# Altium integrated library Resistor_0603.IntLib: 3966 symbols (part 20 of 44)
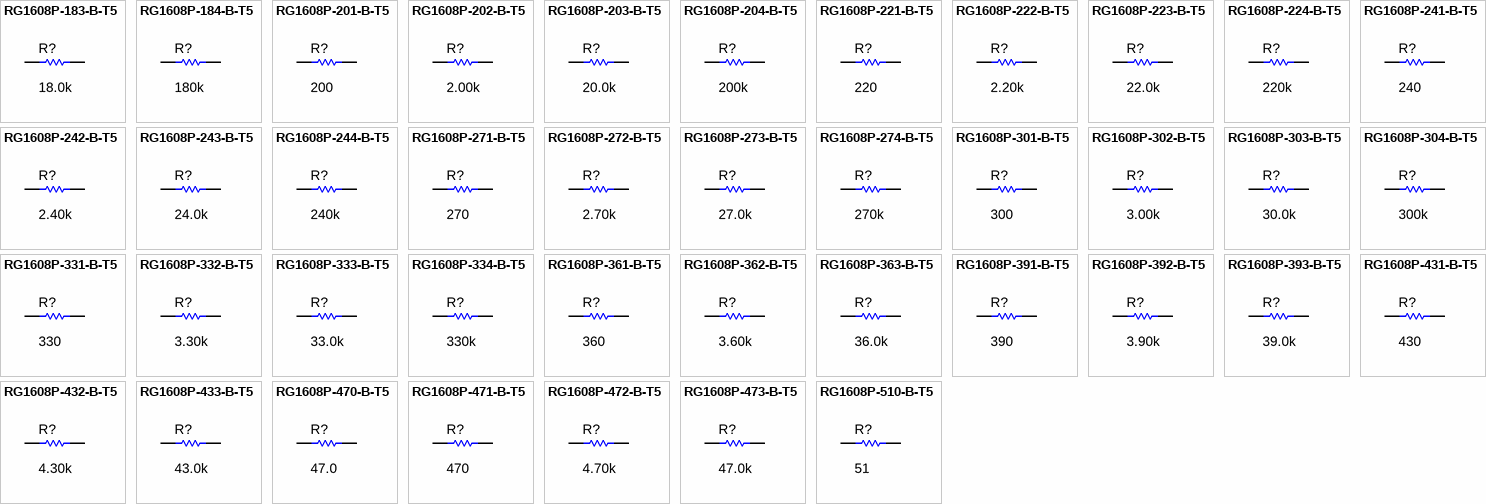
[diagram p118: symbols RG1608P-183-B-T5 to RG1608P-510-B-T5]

## RG1608P-431-B-T5
designator R?  ValueDisplayed: 430  (hidden comment: RG1608P-431-B-T5)
RES, 430, 0.1%, 0.1 W, 0603; Manufacturer: Susumu Co Ltd; CompType: Resistor; Value: 430; Value_Code: 430R; Tolerance_%: 0.1; Value2: 0.1W; VDC_V: 75; TempCo: 25 ppm/C; SizeArea_mm2: 1.28; SizeX_mm: 1.6; SizeY_mm: 0.8; SizeZ_mm: 1; U/M: EA; AEC Category: Q200
signal-integrity model Resistor
simulation model Resistor
footprint 0603
footprint 0603M
footprint 0603L
footprint 0603_HV
footprint 0603S
pins: 1, 2

## RG1608P-432-B-T5
designator R?  ValueDisplayed: 4.30k  (hidden comment: RG1608P-432-B-T5)
RES, 4.30 k, 0.1%, 0.1 W, 0603; Manufacturer: Susumu Co Ltd; CompType: Resistor; Value: 4.30k; Res_ohm: 4300; Value_Code: 4k30; Tolerance_%: 0.1; Value2: 0.1W; VDC_V: 75; TempCo: 25 ppm/C; SizeArea_mm2: 1.28; SizeX_mm: 1.6; SizeY_mm: 0.8; SizeZ_mm: 1; U/M: EA; AEC Category: Q200
signal-integrity model Resistor
simulation model Resistor
footprint 0603
footprint 0603M
footprint 0603L
footprint 0603_HV
footprint 0603S
pins: 1, 2

## RG1608P-433-B-T5
designator R?  ValueDisplayed: 43.0k  (hidden comment: RG1608P-433-B-T5)
RES, 43.0 k, 0.1%, 0.1 W, 0603; Manufacturer: Susumu Co Ltd; CompType: Resistor; Value: 43.0k; Res_ohm: 43000; Value_Code: 43k0; Tolerance_%: 0.1; Value2: 0.1W; VDC_V: 75; TempCo: 25 ppm/C; SizeArea_mm2: 1.28; SizeX_mm: 1.6; SizeY_mm: 0.8; SizeZ_mm: 1; U/M: EA; AEC Category: Q200
signal-integrity model Resistor
simulation model Resistor
footprint 0603
footprint 0603M
footprint 0603L
footprint 0603_HV
footprint 0603S
pins: 1, 2

## RG1608P-470-B-T5
designator R?  ValueDisplayed: 47.0  (hidden comment: RG1608P-470-B-T5)
RES, 47.0, 0.1%, 0.1 W, 0603; Manufacturer: Susumu Co Ltd; CompType: Resistor; Value: 47.0; Res_ohm: 47; Value_Code: 47R0; Tolerance_%: 0.1; Value2: 0.1W; VDC_V: 75; TempCo: 25 ppm/C; SizeArea_mm2: 1.28; SizeX_mm: 1.6; SizeY_mm: 0.8; SizeZ_mm: 1; EIA_Code: E192; U/M: EA; AEC Category: Q200
signal-integrity model Resistor
simulation model Resistor
footprint 0603
footprint 0603M
footprint 0603L
footprint 0603_HV
footprint 0603S
pins: 1, 2

## RG1608P-471-B-T5
designator R?  ValueDisplayed: 470  (hidden comment: RG1608P-471-B-T5)
RES, 470, 0.1%, 0.1 W, 0603; Manufacturer: Susumu Co Ltd; CompType: Resistor; Value: 470; Value_Code: 470R; Tolerance_%: 0.1; Value2: 0.1W; VDC_V: 75; TempCo: 25 ppm/C; SizeArea_mm2: 1.28; SizeX_mm: 1.6; SizeY_mm: 0.8; SizeZ_mm: 1; EIA_Code: E192; U/M: EA; AEC Category: Q200
signal-integrity model Resistor
simulation model Resistor
footprint 0603
footprint 0603M
footprint 0603L
footprint 0603_HV
footprint 0603S
pins: 1, 2

## RG1608P-472-B-T5
designator R?  ValueDisplayed: 4.70k  (hidden comment: RG1608P-472-B-T5)
RES, 4.70 k, 0.1%, 0.1 W, 0603; Manufacturer: Susumu Co Ltd; CompType: Resistor; Value: 4.70k; Res_ohm: 4700; Value_Code: 4k70; Tolerance_%: 0.1; Value2: 0.1W; VDC_V: 75; TempCo: 25 ppm/C; SizeArea_mm2: 1.28; SizeX_mm: 1.6; SizeY_mm: 0.8; SizeZ_mm: 1; EIA_Code: E192; U/M: EA; AEC Category: Q200; Green_Lifecycle: Active; Green_REACh: Passed
signal-integrity model Resistor
simulation model Resistor
footprint 0603
footprint 0603M
footprint 0603L
footprint 0603_HV
footprint 0603S
pins: 1, 2

## RG1608P-473-B-T5
designator R?  ValueDisplayed: 47.0k  (hidden comment: RG1608P-473-B-T5)
RES, 47.0 k, 0.1%, 0.1 W, 0603; Manufacturer: Susumu Co Ltd; CompType: Resistor; Value: 47.0k; Res_ohm: 47000; Value_Code: 47k0; Tolerance_%: 0.1; Value2: 0.1W; VDC_V: 75; TempCo: 25 ppm/C; SizeArea_mm2: 1.28; SizeX_mm: 1.6; SizeY_mm: 0.8; SizeZ_mm: 1; EIA_Code: E192; U/M: EA; AEC Category: Q200
signal-integrity model Resistor
simulation model Resistor
footprint 0603
footprint 0603M
footprint 0603L
footprint 0603_HV
footprint 0603S
pins: 1, 2

## RG1608P-510-B-T5
designator R?  ValueDisplayed: 51  (hidden comment: RG1608P-510-B-T5)
RES, 51, 0.1%, 0.1 W, 0603; Manufacturer: Susumu Co Ltd; CompType: Resistor; Value: 51; Value_Code: 51R0; Tolerance_%: 0.1; Value2: 0.1W; VDC_V: 75; TempCo: 25 ppm/C; SizeArea_mm2: 1.28; SizeX_mm: 1.6; SizeY_mm: 0.8; SizeZ_mm: 1; U/M: EA; AEC Category: Q200
signal-integrity model Resistor
simulation model Resistor
footprint 0603
footprint 0603M
footprint 0603L
footprint 0603_HV
footprint 0603S
pins: 1, 2

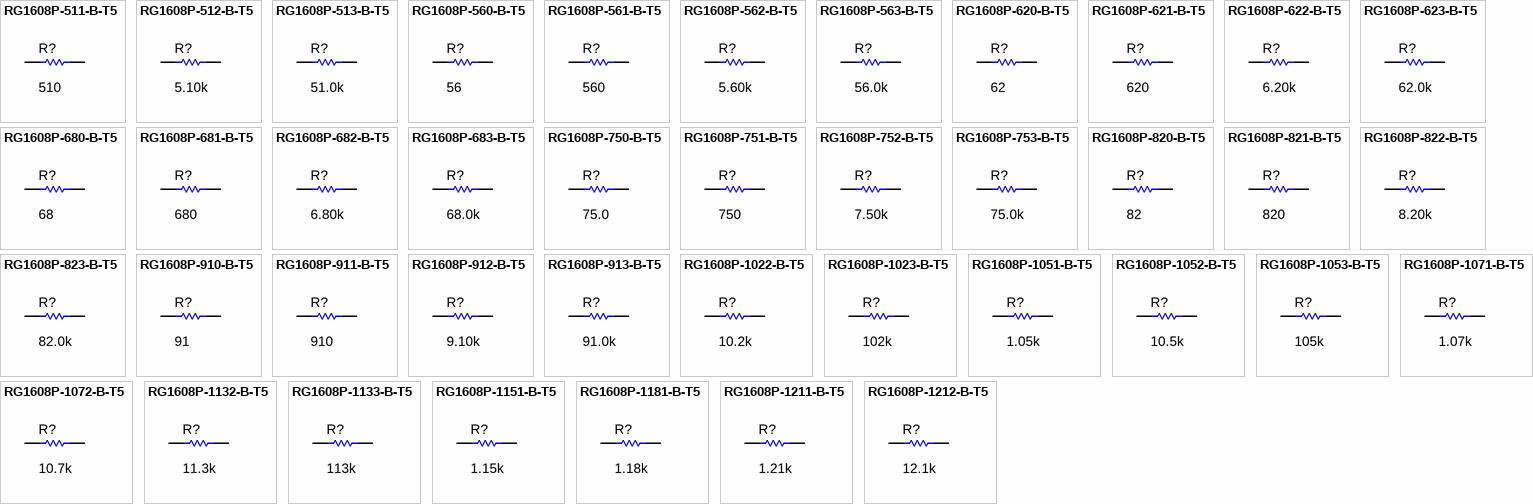
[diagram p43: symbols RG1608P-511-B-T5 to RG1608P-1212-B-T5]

## RG1608P-511-B-T5
designator R?  ValueDisplayed: 510  (hidden comment: RG1608P-511-B-T5)
RES, 510, 0.1%, 0.1 W, 0603; Manufacturer: Susumu Co Ltd; CompType: Resistor; Value: 510; Value_Code: 510R; Tolerance_%: 0.1; Value2: 0.1W; VDC_V: 75; TempCo: 25 ppm/C; SizeArea_mm2: 1.28; SizeX_mm: 1.6; SizeY_mm: 0.8; SizeZ_mm: 1; U/M: EA; AEC Category: Q200
signal-integrity model Resistor
simulation model Resistor
footprint 0603
footprint 0603M
footprint 0603L
footprint 0603_HV
footprint 0603S
pins: 1, 2

## RG1608P-512-B-T5
designator R?  ValueDisplayed: 5.10k  (hidden comment: RG1608P-512-B-T5)
RES, 5.10 k, 0.1%, 0.1 W, 0603; Manufacturer: Susumu Co Ltd; CompType: Resistor; Value: 5.10k; Res_ohm: 5100; Value_Code: 5k10; Tolerance_%: 0.1; Value2: 0.1W; VDC_V: 75; TempCo: 25 ppm/C; SizeArea_mm2: 1.28; SizeX_mm: 1.6; SizeY_mm: 0.8; SizeZ_mm: 1; U/M: EA; AEC Category: Q200
signal-integrity model Resistor
simulation model Resistor
footprint 0603
footprint 0603M
footprint 0603L
footprint 0603_HV
footprint 0603S
pins: 1, 2

## RG1608P-513-B-T5
designator R?  ValueDisplayed: 51.0k  (hidden comment: RG1608P-513-B-T5)
RES, 51.0 k, 0.1%, 0.1 W, 0603; Manufacturer: Susumu Co Ltd; CompType: Resistor; Value: 51.0k; Res_ohm: 51000; Value_Code: 51k0; Tolerance_%: 0.1; Value2: 0.1W; VDC_V: 75; TempCo: 25 ppm/C; SizeArea_mm2: 1.28; SizeX_mm: 1.6; SizeY_mm: 0.8; SizeZ_mm: 1; U/M: EA; AEC Category: Q200
signal-integrity model Resistor
simulation model Resistor
footprint 0603
footprint 0603M
footprint 0603L
footprint 0603_HV
footprint 0603S
pins: 1, 2

## RG1608P-560-B-T5
designator R?  ValueDisplayed: 56  (hidden comment: RG1608P-560-B-T5)
RES, 56, 0.1%, 0.1 W, 0603; Manufacturer: Susumu Co Ltd; CompType: Resistor; Value: 56; Value_Code: 56R0; Tolerance_%: 0.1; Value2: 0.1W; VDC_V: 75; TempCo: 25 ppm/C; SizeArea_mm2: 1.28; SizeX_mm: 1.6; SizeY_mm: 0.8; SizeZ_mm: 1; U/M: EA; AEC Category: Q200
signal-integrity model Resistor
simulation model Resistor
footprint 0603
footprint 0603M
footprint 0603L
footprint 0603_HV
footprint 0603S
pins: 1, 2

## RG1608P-561-B-T5
designator R?  ValueDisplayed: 560  (hidden comment: RG1608P-561-B-T5)
RES, 560, 0.1%, 0.1 W, 0603; Manufacturer: Susumu Co Ltd; CompType: Resistor; Value: 560; Value_Code: 560R; Tolerance_%: 0.1; Value2: 0.1W; VDC_V: 75; TempCo: 25 ppm/C; SizeArea_mm2: 1.28; SizeX_mm: 1.6; SizeY_mm: 0.8; SizeZ_mm: 1; U/M: EA; AEC Category: Q200
signal-integrity model Resistor
simulation model Resistor
footprint 0603
footprint 0603M
footprint 0603L
footprint 0603_HV
footprint 0603S
pins: 1, 2

## RG1608P-562-B-T5
designator R?  ValueDisplayed: 5.60k  (hidden comment: RG1608P-562-B-T5)
RES, 5.60 k, 0.1%, 0.1 W, 0603; Manufacturer: Susumu Co Ltd; CompType: Resistor; Value: 5.60k; Res_ohm: 5600; Value_Code: 5k60; Tolerance_%: 0.1; Value2: 0.1W; VDC_V: 75; TempCo: 25 ppm/C; SizeArea_mm2: 1.28; SizeX_mm: 1.6; SizeY_mm: 0.8; SizeZ_mm: 1; U/M: EA; AEC Category: Q200
signal-integrity model Resistor
simulation model Resistor
footprint 0603
footprint 0603M
footprint 0603L
footprint 0603_HV
footprint 0603S
pins: 1, 2

## RG1608P-563-B-T5
designator R?  ValueDisplayed: 56.0k  (hidden comment: RG1608P-563-B-T5)
RES, 56.0 k, 0.1%, 0.1 W, 0603; Manufacturer: Susumu Co Ltd; CompType: Resistor; Value: 56.0k; Res_ohm: 56000; Value_Code: 56k0; Tolerance_%: 0.1; Value2: 0.1W; VDC_V: 75; TempCo: 25 ppm/C; SizeArea_mm2: 1.28; SizeX_mm: 1.6; SizeY_mm: 0.8; SizeZ_mm: 1; U/M: EA; AEC Category: Q200
signal-integrity model Resistor
simulation model Resistor
footprint 0603
footprint 0603M
footprint 0603L
footprint 0603_HV
footprint 0603S
pins: 1, 2

## RG1608P-620-B-T5
designator R?  ValueDisplayed: 62  (hidden comment: RG1608P-620-B-T5)
RES, 62, 0.1%, 0.1 W, 0603; Manufacturer: Susumu Co Ltd; CompType: Resistor; Value: 62; Value_Code: 62R0; Tolerance_%: 0.1; Value2: 0.1W; VDC_V: 75; TempCo: 25 ppm/C; SizeArea_mm2: 1.28; SizeX_mm: 1.6; SizeY_mm: 0.8; SizeZ_mm: 1; U/M: EA; AEC Category: Q200
signal-integrity model Resistor
simulation model Resistor
footprint 0603
footprint 0603M
footprint 0603L
footprint 0603_HV
footprint 0603S
pins: 1, 2

## RG1608P-621-B-T5
designator R?  ValueDisplayed: 620  (hidden comment: RG1608P-621-B-T5)
RES, 620, 0.1%, 0.1 W, 0603; Manufacturer: Susumu Co Ltd; CompType: Resistor; Value: 620; Value_Code: 620R; Tolerance_%: 0.1; Value2: 0.1W; VDC_V: 75; TempCo: 25 ppm/C; SizeArea_mm2: 1.28; SizeX_mm: 1.6; SizeY_mm: 0.8; SizeZ_mm: 1; U/M: EA; AEC Category: Q200
signal-integrity model Resistor
simulation model Resistor
footprint 0603
footprint 0603M
footprint 0603L
footprint 0603_HV
footprint 0603S
pins: 1, 2

## RG1608P-622-B-T5
designator R?  ValueDisplayed: 6.20k  (hidden comment: RG1608P-622-B-T5)
RES, 6.20 k, 0.1%, 0.1 W, 0603; Manufacturer: Susumu Co Ltd; CompType: Resistor; Value: 6.20k; Res_ohm: 6200; Value_Code: 6k20; Tolerance_%: 0.1; Value2: 0.1W; VDC_V: 75; TempCo: 25 ppm/C; SizeArea_mm2: 1.28; SizeX_mm: 1.6; SizeY_mm: 0.8; SizeZ_mm: 1; U/M: EA; AEC Category: Q200
signal-integrity model Resistor
simulation model Resistor
footprint 0603
footprint 0603M
footprint 0603L
footprint 0603_HV
footprint 0603S
pins: 1, 2

## RG1608P-623-B-T5
designator R?  ValueDisplayed: 62.0k  (hidden comment: RG1608P-623-B-T5)
RES, 62.0 k, 0.1%, 0.1 W, 0603; Manufacturer: Susumu Co Ltd; CompType: Resistor; Value: 62.0k; Res_ohm: 62000; Value_Code: 62k0; Tolerance_%: 0.1; Value2: 0.1W; VDC_V: 75; TempCo: 25 ppm/C; SizeArea_mm2: 1.28; SizeX_mm: 1.6; SizeY_mm: 0.8; SizeZ_mm: 1; U/M: EA; AEC Category: Q200
signal-integrity model Resistor
simulation model Resistor
footprint 0603
footprint 0603M
footprint 0603L
footprint 0603_HV
footprint 0603S
pins: 1, 2

## RG1608P-680-B-T5
designator R?  ValueDisplayed: 68  (hidden comment: RG1608P-680-B-T5)
RES, 68, 0.1%, 0.1 W, 0603; Manufacturer: Susumu Co Ltd; CompType: Resistor; Value: 68; Value_Code: 68R0; Tolerance_%: 0.1; Value2: 0.1W; VDC_V: 75; TempCo: 25 ppm/C; SizeArea_mm2: 1.28; SizeX_mm: 1.6; SizeY_mm: 0.8; SizeZ_mm: 1; U/M: EA; AEC Category: Q200
signal-integrity model Resistor
simulation model Resistor
footprint 0603
footprint 0603M
footprint 0603L
footprint 0603_HV
footprint 0603S
pins: 1, 2

## RG1608P-681-B-T5
designator R?  ValueDisplayed: 680  (hidden comment: RG1608P-681-B-T5)
RES, 680, 0.1%, 0.1 W, 0603; Manufacturer: Susumu Co Ltd; CompType: Resistor; Value: 680; Value_Code: 680R; Tolerance_%: 0.1; Value2: 0.1W; VDC_V: 75; TempCo: 25 ppm/C; SizeArea_mm2: 1.28; SizeX_mm: 1.6; SizeY_mm: 0.8; SizeZ_mm: 1; U/M: EA; AEC Category: Q200
signal-integrity model Resistor
simulation model Resistor
footprint 0603
footprint 0603M
footprint 0603L
footprint 0603_HV
footprint 0603S
pins: 1, 2

## RG1608P-682-B-T5
designator R?  ValueDisplayed: 6.80k  (hidden comment: RG1608P-682-B-T5)
RES, 6.80 k, 0.1%, 0.1 W, 0603; Manufacturer: Susumu Co Ltd; CompType: Resistor; Value: 6.80k; Res_ohm: 6800; Value_Code: 6k80; Tolerance_%: 0.1; Value2: 0.1W; VDC_V: 75; TempCo: 25 ppm/C; SizeArea_mm2: 1.28; SizeX_mm: 1.6; SizeY_mm: 0.8; SizeZ_mm: 1; U/M: EA; AEC Category: Q200
signal-integrity model Resistor
simulation model Resistor
footprint 0603
footprint 0603M
footprint 0603L
footprint 0603_HV
footprint 0603S
pins: 1, 2

## RG1608P-683-B-T5
designator R?  ValueDisplayed: 68.0k  (hidden comment: RG1608P-683-B-T5)
RES, 68.0 k, 0.1%, 0.1 W, 0603; Manufacturer: Susumu Co Ltd; CompType: Resistor; Value: 68.0k; Res_ohm: 68000; Value_Code: 68k0; Tolerance_%: 0.1; Value2: 0.1W; VDC_V: 75; TempCo: 25 ppm/C; SizeArea_mm2: 1.28; SizeX_mm: 1.6; SizeY_mm: 0.8; SizeZ_mm: 1; U/M: EA; AEC Category: Q200
signal-integrity model Resistor
simulation model Resistor
footprint 0603
footprint 0603M
footprint 0603L
footprint 0603_HV
footprint 0603S
pins: 1, 2

## RG1608P-750-B-T5
designator R?  ValueDisplayed: 75.0  (hidden comment: RG1608P-750-B-T5)
RES, 75.0, 0.1%, 0.1 W, 0603; Manufacturer: Susumu Co Ltd; CompType: Resistor; Value: 75.0; Res_ohm: 75; Value_Code: 75R0; Tolerance_%: 0.1; Value2: 0.1W; TempCo: 25 ppm/C; SizeArea_mm2: 1.28; SizeX_mm: 1.6; SizeY_mm: 0.8; SizeZ_mm: 1; EIA_Code: E192; U/M: EA; AEC Category: Q200
signal-integrity model Resistor
simulation model Resistor
footprint 0603
footprint 0603M
footprint 0603L
footprint 0603_HV
footprint 0603S
pins: 1, 2

## RG1608P-751-B-T5
designator R?  ValueDisplayed: 750  (hidden comment: RG1608P-751-B-T5)
RES, 750, 0.1%, 0.1 W, 0603; Manufacturer: Susumu Co Ltd; CompType: Resistor; Value: 750; Value_Code: 750R; Tolerance_%: 0.1; Value2: 0.1W; VDC_V: 75; TempCo: 25 ppm/C; SizeArea_mm2: 1.28; SizeX_mm: 1.6; SizeY_mm: 0.8; SizeZ_mm: 1; EIA_Code: E192; U/M: EA; AEC Category: Q200
signal-integrity model Resistor
simulation model Resistor
footprint 0603
footprint 0603M
footprint 0603L
footprint 0603_HV
footprint 0603S
pins: 1, 2

## RG1608P-752-B-T5
designator R?  ValueDisplayed: 7.50k  (hidden comment: RG1608P-752-B-T5)
RES, 7.50 k, 0.1%, 0.1 W, 0603; Manufacturer: Susumu Co Ltd; CompType: Resistor; Value: 7.50k; Res_ohm: 7500; Value_Code: 7k50; Tolerance_%: 0.1; Value2: 0.1W; VDC_V: 75; TempCo: 25 ppm/C; SizeArea_mm2: 1.28; SizeX_mm: 1.6; SizeY_mm: 0.8; SizeZ_mm: 1; EIA_Code: E192; U/M: EA; AEC Category: Q200
signal-integrity model Resistor
simulation model Resistor
footprint 0603
footprint 0603M
footprint 0603L
footprint 0603_HV
footprint 0603S
pins: 1, 2

## RG1608P-753-B-T5
designator R?  ValueDisplayed: 75.0k  (hidden comment: RG1608P-753-B-T5)
RES, 75.0 k, 0.1%, 0.1 W, 0603; Manufacturer: Susumu Co Ltd; CompType: Resistor; Value: 75.0k; Res_ohm: 75000; Value_Code: 75k0; Tolerance_%: 0.1; Value2: 0.1W; VDC_V: 75; TempCo: 25 ppm/C; SizeArea_mm2: 1.28; SizeX_mm: 1.6; SizeY_mm: 0.8; SizeZ_mm: 1; EIA_Code: E192; U/M: EA; AEC Category: Q200
signal-integrity model Resistor
simulation model Resistor
footprint 0603
footprint 0603M
footprint 0603L
footprint 0603_HV
footprint 0603S
pins: 1, 2

## RG1608P-820-B-T5
designator R?  ValueDisplayed: 82  (hidden comment: RG1608P-820-B-T5)
RES, 82, 0.1%, 0.1 W, 0603; Manufacturer: Susumu Co Ltd; CompType: Resistor; Value: 82; Value_Code: 82R0; Tolerance_%: 0.1; Value2: 0.1W; VDC_V: 75; TempCo: 25 ppm/C; SizeArea_mm2: 1.28; SizeX_mm: 1.6; SizeY_mm: 0.8; SizeZ_mm: 1; U/M: EA; AEC Category: Q200
signal-integrity model Resistor
simulation model Resistor
footprint 0603
footprint 0603M
footprint 0603L
footprint 0603_HV
footprint 0603S
pins: 1, 2

## RG1608P-821-B-T5
designator R?  ValueDisplayed: 820  (hidden comment: RG1608P-821-B-T5)
RES, 820, 0.1%, 0.1 W, 0603; Manufacturer: Susumu Co Ltd; CompType: Resistor; Value: 820; Value_Code: 820R; Tolerance_%: 0.1; Value2: 0.1W; VDC_V: 75; TempCo: 25 ppm/C; SizeArea_mm2: 1.28; SizeX_mm: 1.6; SizeY_mm: 0.8; SizeZ_mm: 1; U/M: EA; AEC Category: Q200
signal-integrity model Resistor
simulation model Resistor
footprint 0603
footprint 0603M
footprint 0603L
footprint 0603_HV
footprint 0603S
pins: 1, 2

## RG1608P-822-B-T5
designator R?  ValueDisplayed: 8.20k  (hidden comment: RG1608P-822-B-T5)
RES, 8.20 k, 0.1%, 0.1 W, 0603; Manufacturer: Susumu Co Ltd; CompType: Resistor; Value: 8.20k; Res_ohm: 8200; Value_Code: 8k20; Tolerance_%: 0.1; Value2: 0.1W; VDC_V: 75; TempCo: 25 ppm/C; SizeArea_mm2: 1.28; SizeX_mm: 1.6; SizeY_mm: 0.8; SizeZ_mm: 1; U/M: EA; AEC Category: Q200
signal-integrity model Resistor
simulation model Resistor
footprint 0603
footprint 0603M
footprint 0603L
footprint 0603_HV
footprint 0603S
pins: 1, 2

## RG1608P-823-B-T5
designator R?  ValueDisplayed: 82.0k  (hidden comment: RG1608P-823-B-T5)
RES, 82.0 k, 0.1%, 0.1 W, 0603; Manufacturer: Susumu Co Ltd; CompType: Resistor; Value: 82.0k; Res_ohm: 82000; Value_Code: 82k0; Tolerance_%: 0.1; Value2: 0.1W; VDC_V: 75; TempCo: 25 ppm/C; SizeArea_mm2: 1.28; SizeX_mm: 1.6; SizeY_mm: 0.8; SizeZ_mm: 1; U/M: EA; AEC Category: Q200
signal-integrity model Resistor
simulation model Resistor
footprint 0603
footprint 0603M
footprint 0603L
footprint 0603_HV
footprint 0603S
pins: 1, 2

## RG1608P-910-B-T5
designator R?  ValueDisplayed: 91  (hidden comment: RG1608P-910-B-T5)
RES, 91, 0.1%, 0.1 W, 0603; Manufacturer: Susumu Co Ltd; CompType: Resistor; Value: 91; Value_Code: 91R0; Tolerance_%: 0.1; Value2: 0.1W; VDC_V: 75; TempCo: 25 ppm/C; SizeArea_mm2: 1.28; SizeX_mm: 1.6; SizeY_mm: 0.8; SizeZ_mm: 1; U/M: EA; AEC Category: Q200
signal-integrity model Resistor
simulation model Resistor
footprint 0603
footprint 0603M
footprint 0603L
footprint 0603_HV
footprint 0603S
pins: 1, 2

## RG1608P-911-B-T5
designator R?  ValueDisplayed: 910  (hidden comment: RG1608P-911-B-T5)
RES, 910, 0.1%, 0.1 W, 0603; Manufacturer: Susumu Co Ltd; CompType: Resistor; Value: 910; Value_Code: 910R; Tolerance_%: 0.1; Value2: 0.1W; VDC_V: 75; TempCo: 25 ppm/C; SizeArea_mm2: 1.28; SizeX_mm: 1.6; SizeY_mm: 0.8; SizeZ_mm: 1; U/M: EA; AEC Category: Q200
signal-integrity model Resistor
simulation model Resistor
footprint 0603
footprint 0603M
footprint 0603L
footprint 0603_HV
footprint 0603S
pins: 1, 2

## RG1608P-912-B-T5
designator R?  ValueDisplayed: 9.10k  (hidden comment: RG1608P-912-B-T5)
RES, 9.10 k, 0.1%, 0.1 W, 0603; Manufacturer: Susumu Co Ltd; CompType: Resistor; Value: 9.10k; Res_ohm: 9100; Value_Code: 9k10; Tolerance_%: 0.1; Value2: 0.1W; VDC_V: 75; TempCo: 25 ppm/C; SizeArea_mm2: 1.28; SizeX_mm: 1.6; SizeY_mm: 0.8; SizeZ_mm: 1; U/M: EA; AEC Category: Q200
signal-integrity model Resistor
simulation model Resistor
footprint 0603
footprint 0603M
footprint 0603L
footprint 0603_HV
footprint 0603S
pins: 1, 2

## RG1608P-913-B-T5
designator R?  ValueDisplayed: 91.0k  (hidden comment: RG1608P-913-B-T5)
RES, 91.0 k, 0.1%, 0.1 W, 0603; Manufacturer: Susumu Co Ltd; CompType: Resistor; Value: 91.0k; Res_ohm: 91000; Value_Code: 91k0; Tolerance_%: 0.1; Value2: 0.1W; VDC_V: 75; TempCo: 25 ppm/C; SizeArea_mm2: 1.28; SizeX_mm: 1.6; SizeY_mm: 0.8; SizeZ_mm: 1; U/M: EA; AEC Category: Q200
signal-integrity model Resistor
simulation model Resistor
footprint 0603
footprint 0603M
footprint 0603L
footprint 0603_HV
footprint 0603S
pins: 1, 2

## RG1608P-1022-B-T5
designator R?  ValueDisplayed: 10.2k  (hidden comment: RG1608P-1022-B-T5)
RES, 10.2 k, 0.1%, 0.1 W, 0603; Manufacturer: Susumu Co Ltd; CompType: Resistor; Value: 10.2k; Res_ohm: 10200; Value_Code: 10k2; Tolerance_%: 0.1; Value2: 0.1W; VDC_V: 75; TempCo: 25 ppm/C; SizeArea_mm2: 1.28; SizeX_mm: 1.6; SizeY_mm: 0.8; SizeZ_mm: 1; EIA_Code: E192; U/M: EA; AEC Category: Q200
signal-integrity model Resistor
simulation model Resistor
footprint 0603
footprint 0603M
footprint 0603L
footprint 0603_HV
footprint 0603S
pins: 1, 2

## RG1608P-1023-B-T5
designator R?  ValueDisplayed: 102k  (hidden comment: RG1608P-1023-B-T5)
RES, 102 k, 0.1%, 0.1 W, 0603; Manufacturer: Susumu Co Ltd; CompType: Resistor; Value: 102k; Res_ohm: 102000; Tolerance_%: 0.1; Value2: 0.1W; VDC_V: 75; TempCo: 25 ppm/C; SizeArea_mm2: 1.28; SizeX_mm: 1.6; SizeY_mm: 0.8; SizeZ_mm: 1; EIA_Code: E192; U/M: EA; AEC Category: Q200; Green_Lifecycle: Active; Green_REACh: Passed
signal-integrity model Resistor
simulation model Resistor
footprint 0603
footprint 0603M
footprint 0603L
footprint 0603_HV
footprint 0603S
pins: 1, 2

## RG1608P-1051-B-T5
designator R?  ValueDisplayed: 1.05k  (hidden comment: RG1608P-1051-B-T5)
RES, 1.05 k, 0.1%, 0.1 W, 0603; Manufacturer: Susumu Co Ltd; CompType: Resistor; Value: 1.05k; Res_ohm: 1050; Value_Code: 1k05; Tolerance_%: 0.1; Value2: 0.1W; VDC_V: 75; TempCo: 25 ppm/C; SizeArea_mm2: 1.28; SizeX_mm: 1.6; SizeY_mm: 0.8; SizeZ_mm: 1; EIA_Code: E192; U/M: EA; AEC Category: Q200
signal-integrity model Resistor
simulation model Resistor
footprint 0603
footprint 0603M
footprint 0603L
footprint 0603_HV
footprint 0603S
pins: 1, 2

## RG1608P-1052-B-T5
designator R?  ValueDisplayed: 10.5k  (hidden comment: RG1608P-1052-B-T5)
RES, 10.5 k, 0.1%, 0.1 W, 0603; Manufacturer: Susumu Co Ltd; CompType: Resistor; Value: 10.5k; Res_ohm: 10500; Value_Code: 10k5; Tolerance_%: 0.1; Value2: 0.1W; VDC_V: 75; TempCo: 25 ppm/C; SizeArea_mm2: 1.28; SizeX_mm: 1.6; SizeY_mm: 0.8; SizeZ_mm: 1; EIA_Code: E192; U/M: EA; AEC Category: Q200
signal-integrity model Resistor
simulation model Resistor
footprint 0603
footprint 0603M
footprint 0603L
footprint 0603_HV
footprint 0603S
pins: 1, 2

## RG1608P-1053-B-T5
designator R?  ValueDisplayed: 105k  (hidden comment: RG1608P-1053-B-T5)
RES, 105 k, 0.1%, 0.1 W, 0603; Manufacturer: Susumu Co Ltd; CompType: Resistor; Value: 105k; Res_ohm: 105000; Tolerance_%: 0.1; Value2: 0.1W; VDC_V: 75; TempCo: 25 ppm/C; SizeArea_mm2: 1.28; SizeX_mm: 1.6; SizeY_mm: 0.8; SizeZ_mm: 1; EIA_Code: E192; U/M: EA; AEC Category: Q200
signal-integrity model Resistor
simulation model Resistor
footprint 0603
footprint 0603M
footprint 0603L
footprint 0603_HV
footprint 0603S
pins: 1, 2

## RG1608P-1071-B-T5
designator R?  ValueDisplayed: 1.07k  (hidden comment: RG1608P-1071-B-T5)
RES, 1.07 k, 0.1%, 0.1 W, 0603; Manufacturer: Susumu Co Ltd; CompType: Resistor; Value: 1.07k; Res_ohm: 1070; Value_Code: 1k07; Tolerance_%: 0.1; Value2: 0.1W; VDC_V: 75; TempCo: 25 ppm/C; SizeArea_mm2: 1.28; SizeX_mm: 1.6; SizeY_mm: 0.8; SizeZ_mm: 1; EIA_Code: E192; U/M: EA; AEC Category: Q200
signal-integrity model Resistor
simulation model Resistor
footprint 0603
footprint 0603M
footprint 0603L
footprint 0603_HV
footprint 0603S
pins: 1, 2

## RG1608P-1072-B-T5
designator R?  ValueDisplayed: 10.7k  (hidden comment: RG1608P-1072-B-T5)
RES, 10.7 k, 0.1%, 0.1 W, 0603; Manufacturer: Susumu Co Ltd; CompType: Resistor; Value: 10.7k; Res_ohm: 10700; Value_Code: 10k7; Tolerance_%: 0.1; Value2: 0.1W; VDC_V: 75; TempCo: 25 ppm/C; SizeArea_mm2: 1.28; SizeX_mm: 1.6; SizeY_mm: 0.8; SizeZ_mm: 1; EIA_Code: E192; U/M: EA; AEC Category: Q200
signal-integrity model Resistor
simulation model Resistor
footprint 0603
footprint 0603M
footprint 0603L
footprint 0603_HV
footprint 0603S
pins: 1, 2

## RG1608P-1132-B-T5
designator R?  ValueDisplayed: 11.3k  (hidden comment: RG1608P-1132-B-T5)
RES, 11.3 k, 0.1%, 0.1 W, 0603; Manufacturer: Susumu Co Ltd; CompType: Resistor; Value: 11.3k; Res_ohm: 11300; Value_Code: 11k3; Tolerance_%: 0.1; Value2: 0.1W; VDC_V: 75; TempCo: 25 ppm/C; SizeArea_mm2: 1.28; SizeX_mm: 1.6; SizeY_mm: 0.8; SizeZ_mm: 1; EIA_Code: E192; U/M: EA; AEC Category: Q200; Green_Lifecycle: Active; Green_REACh: Passed
signal-integrity model Resistor
simulation model Resistor
footprint 0603
footprint 0603M
footprint 0603L
footprint 0603_HV
footprint 0603S
pins: 1, 2

## RG1608P-1133-B-T5
designator R?  ValueDisplayed: 113k  (hidden comment: RG1608P-1133-B-T5)
RES, 113 k, 0.1%, 0.1 W, 0603; Manufacturer: Susumu Co Ltd; CompType: Resistor; Value: 113k; Res_ohm: 113000; Tolerance_%: 0.1; Value2: 0.1W; VDC_V: 75; TempCo: 25 ppm/C; SizeArea_mm2: 1.28; SizeX_mm: 1.6; SizeY_mm: 0.8; SizeZ_mm: 1; EIA_Code: E192; U/M: EA; AEC Category: Q200
signal-integrity model Resistor
simulation model Resistor
footprint 0603
footprint 0603M
footprint 0603L
footprint 0603_HV
footprint 0603S
pins: 1, 2

## RG1608P-1151-B-T5
designator R?  ValueDisplayed: 1.15k  (hidden comment: RG1608P-1151-B-T5)
RES, 1.15 k, 0.1%, 0.1 W, 0603; Manufacturer: Susumu Co Ltd; CompType: Resistor; Value: 1.15k; Res_ohm: 1150; Value_Code: 1k15; Tolerance_%: 0.1; Value2: 0.1W; VDC_V: 75; TempCo: 25 ppm/C; SizeArea_mm2: 1.28; SizeX_mm: 1.6; SizeY_mm: 0.8; SizeZ_mm: 1; EIA_Code: E192; U/M: EA; AEC Category: Q200
signal-integrity model Resistor
simulation model Resistor
footprint 0603
footprint 0603M
footprint 0603L
footprint 0603_HV
footprint 0603S
pins: 1, 2

## RG1608P-1181-B-T5
designator R?  ValueDisplayed: 1.18k  (hidden comment: RG1608P-1181-B-T5)
RES, 1.18 k, 0.1%, 0.1 W, 0603; Manufacturer: Susumu Co Ltd; CompType: Resistor; Value: 1.18k; Res_ohm: 1180; Value_Code: 1k18; Tolerance_%: 0.1; Value2: 0.1W; VDC_V: 75; TempCo: 25 ppm/C; SizeArea_mm2: 1.28; SizeX_mm: 1.6; SizeY_mm: 0.8; SizeZ_mm: 1; EIA_Code: E192; U/M: EA; AEC Category: Q200
signal-integrity model Resistor
simulation model Resistor
footprint 0603
footprint 0603M
footprint 0603L
footprint 0603_HV
footprint 0603S
pins: 1, 2

## RG1608P-1211-B-T5
designator R?  ValueDisplayed: 1.21k  (hidden comment: RG1608P-1211-B-T5)
RES, 1.21 k, 0.1%, 0.1 W, 0603; Manufacturer: Susumu Co Ltd; CompType: Resistor; Value: 1.21k; Res_ohm: 1210; Value_Code: 1k21; Tolerance_%: 0.1; Value2: 0.1W; VDC_V: 75; TempCo: 25 ppm/C; SizeArea_mm2: 1.28; SizeX_mm: 1.6; SizeY_mm: 0.8; SizeZ_mm: 1; EIA_Code: E192; U/M: EA; AEC Category: Q200
signal-integrity model Resistor
simulation model Resistor
footprint 0603
footprint 0603M
footprint 0603L
footprint 0603_HV
footprint 0603S
pins: 1, 2

## RG1608P-1212-B-T5
designator R?  ValueDisplayed: 12.1k  (hidden comment: RG1608P-1212-B-T5)
RES, 12.1 k, 0.1%, 0.1 W, 0603; Manufacturer: Susumu Co Ltd; CompType: Resistor; Value: 12.1k; Res_ohm: 12100; Value_Code: 12k1; Tolerance_%: 0.1; Value2: 0.1W; VDC_V: 75; TempCo: 25 ppm/C; SizeArea_mm2: 1.28; SizeX_mm: 1.6; SizeY_mm: 0.8; SizeZ_mm: 1; EIA_Code: E192; U/M: EA; AEC Category: Q200
signal-integrity model Resistor
simulation model Resistor
footprint 0603
footprint 0603M
footprint 0603L
footprint 0603_HV
footprint 0603S
pins: 1, 2

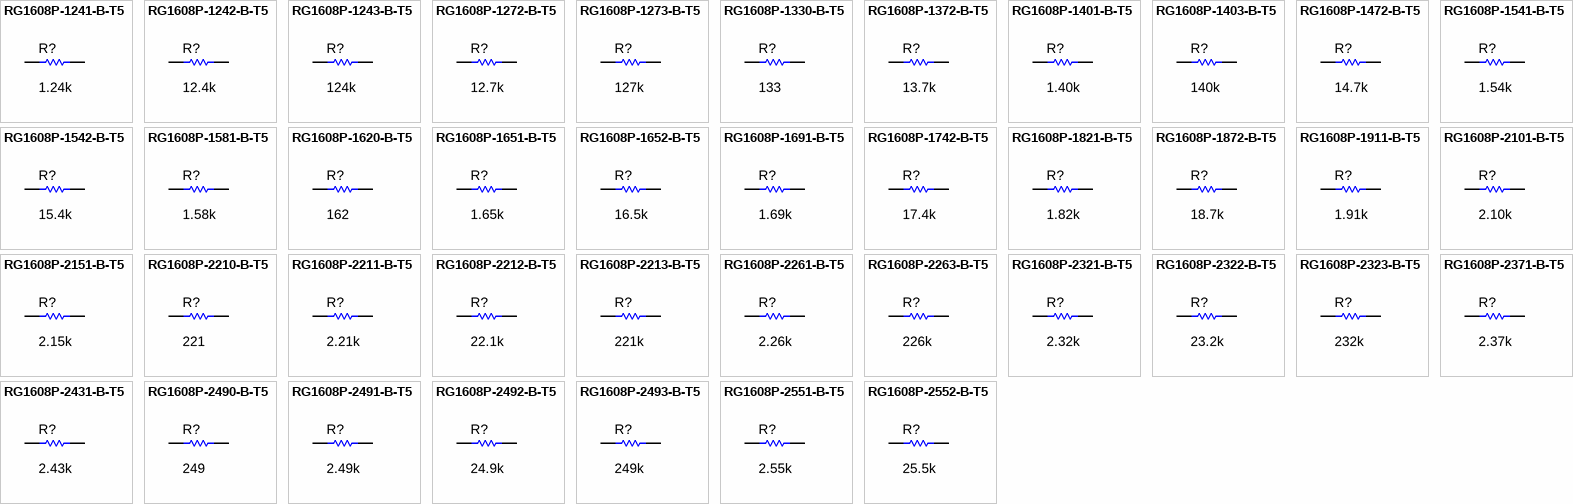
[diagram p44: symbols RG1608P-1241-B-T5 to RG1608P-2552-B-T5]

## RG1608P-1241-B-T5
designator R?  ValueDisplayed: 1.24k  (hidden comment: RG1608P-1241-B-T5)
RES, 1.24 k, 0.1%, 0.1 W, 0603; Manufacturer: Susumu Co Ltd; CompType: Resistor; Value: 1.24k; Res_ohm: 1240; Value_Code: 1k24; Tolerance_%: 0.1; Value2: 0.1W; VDC_V: 75; TempCo: 25 ppm/C; SizeArea_mm2: 1.28; SizeX_mm: 1.6; SizeY_mm: 0.8; SizeZ_mm: 1; EIA_Code: E192; U/M: EA; AEC Category: Q200; Green_Lifecycle: Active; Green_REACh: Passed
signal-integrity model Resistor
simulation model Resistor
footprint 0603
footprint 0603M
footprint 0603L
footprint 0603_HV
footprint 0603S
pins: 1, 2

## RG1608P-1242-B-T5
designator R?  ValueDisplayed: 12.4k  (hidden comment: RG1608P-1242-B-T5)
RES, 12.4 k, 0.1%, 0.1 W, 0603; Manufacturer: Susumu Co Ltd; CompType: Resistor; Value: 12.4k; Res_ohm: 12400; Value_Code: 12k4; Tolerance_%: 0.1; Value2: 0.1W; VDC_V: 75; TempCo: 25 ppm/C; SizeArea_mm2: 1.28; SizeX_mm: 1.6; SizeY_mm: 0.8; SizeZ_mm: 1; EIA_Code: E192; U/M: EA; AEC Category: Q200
signal-integrity model Resistor
simulation model Resistor
footprint 0603
footprint 0603M
footprint 0603L
footprint 0603_HV
footprint 0603S
pins: 1, 2

## RG1608P-1243-B-T5
designator R?  ValueDisplayed: 124k  (hidden comment: RG1608P-1243-B-T5)
RES, 124 k, 0.1%, 0.1 W, 0603; Manufacturer: Susumu Co Ltd; CompType: Resistor; Value: 124k; Res_ohm: 124000; Tolerance_%: 0.1; Value2: 0.1W; VDC_V: 75; TempCo: 25 ppm/C; SizeArea_mm2: 1.28; SizeX_mm: 1.6; SizeY_mm: 0.8; SizeZ_mm: 1; EIA_Code: E192; U/M: EA; AEC Category: Q200
signal-integrity model Resistor
simulation model Resistor
footprint 0603
footprint 0603M
footprint 0603L
footprint 0603_HV
footprint 0603S
pins: 1, 2

## RG1608P-1272-B-T5
designator R?  ValueDisplayed: 12.7k  (hidden comment: RG1608P-1272-B-T5)
RES, 12.7 k, 0.1%, 0.1 W, 0603; Manufacturer: Susumu Co Ltd; CompType: Resistor; Value: 12.7k; Res_ohm: 12700; Value_Code: 12k7; Tolerance_%: 0.1; Value2: 0.1W; VDC_V: 75; TempCo: 25 ppm/C; SizeArea_mm2: 1.28; SizeX_mm: 1.6; SizeY_mm: 0.8; SizeZ_mm: 1; EIA_Code: E192; U/M: EA; AEC Category: Q200
signal-integrity model Resistor
simulation model Resistor
footprint 0603
footprint 0603M
footprint 0603L
footprint 0603_HV
footprint 0603S
pins: 1, 2

## RG1608P-1273-B-T5
designator R?  ValueDisplayed: 127k  (hidden comment: RG1608P-1273-B-T5)
RES, 127 k, 0.1%, 0.1 W, 0603; Manufacturer: Susumu Co Ltd; CompType: Resistor; Value: 127k; Res_ohm: 127000; Tolerance_%: 0.1; Value2: 0.1W; VDC_V: 75; TempCo: 25 ppm/C; SizeArea_mm2: 1.28; SizeX_mm: 1.6; SizeY_mm: 0.8; SizeZ_mm: 1; EIA_Code: E192; U/M: EA; AEC Category: Q200
signal-integrity model Resistor
simulation model Resistor
footprint 0603
footprint 0603M
footprint 0603L
footprint 0603_HV
footprint 0603S
pins: 1, 2

## RG1608P-1330-B-T5
designator R?  ValueDisplayed: 133  (hidden comment: RG1608P-1330-B-T5)
RES, 133, 0.1%, 0.1 W, 0603; Manufacturer: Susumu Co Ltd; CompType: Resistor; Value: 133; Value_Code: 133R; Tolerance_%: 0.1; Value2: 0.1W; VDC_V: 75; TempCo: 25 ppm/C; SizeArea_mm2: 1.28; SizeX_mm: 1.6; SizeY_mm: 0.8; SizeZ_mm: 1; EIA_Code: E192; U/M: EA; AEC Category: Q200; Green_Lifecycle: Active; Green_REACh: Passed
signal-integrity model Resistor
simulation model Resistor
footprint 0603
footprint 0603M
footprint 0603L
footprint 0603_HV
footprint 0603S
pins: 1, 2

## RG1608P-1372-B-T5
designator R?  ValueDisplayed: 13.7k  (hidden comment: RG1608P-1372-B-T5)
RES, 13.7 k, 0.1%, 0.1 W, 0603; Manufacturer: Susumu Co Ltd; CompType: Resistor; Value: 13.7k; Res_ohm: 13700; Value_Code: 13k7; Tolerance_%: 0.1; Value2: 0.1W; VDC_V: 75; TempCo: 25 ppm/C; SizeArea_mm2: 1.28; SizeX_mm: 1.6; SizeY_mm: 0.8; SizeZ_mm: 1; EIA_Code: E192; U/M: EA; AEC Category: Q200; Green_Lifecycle: Active; Green_REACh: Passed
signal-integrity model Resistor
simulation model Resistor
footprint 0603
footprint 0603M
footprint 0603L
footprint 0603_HV
footprint 0603S
pins: 1, 2

## RG1608P-1401-B-T5
designator R?  ValueDisplayed: 1.40k  (hidden comment: RG1608P-1401-B-T5)
RES, 1.40 k, 0.1%, 0.1 W, 0603; Manufacturer: Susumu Co Ltd; CompType: Resistor; Value: 1.40k; Res_ohm: 1400; Value_Code: 1k40; Tolerance_%: 0.1; Value2: 0.1W; VDC_V: 75; TempCo: 25 ppm/C; SizeArea_mm2: 1.28; SizeX_mm: 1.6; SizeY_mm: 0.8; SizeZ_mm: 1; EIA_Code: E192; U/M: EA; AEC Category: Q200
signal-integrity model Resistor
simulation model Resistor
footprint 0603
footprint 0603M
footprint 0603L
footprint 0603_HV
footprint 0603S
pins: 1, 2

## RG1608P-1403-B-T5
designator R?  ValueDisplayed: 140k  (hidden comment: RG1608P-1403-B-T5)
RES, 140 k, 0.1%, 0.1 W, 0603; Manufacturer: Susumu Co Ltd; CompType: Resistor; Value: 140k; Res_ohm: 140000; Tolerance_%: 0.1; Value2: 0.1W; VDC_V: 75; TempCo: 25 ppm/C; SizeArea_mm2: 1.28; SizeX_mm: 1.6; SizeY_mm: 0.8; SizeZ_mm: 1; EIA_Code: E192; U/M: EA; AEC Category: Q200
signal-integrity model Resistor
simulation model Resistor
footprint 0603
footprint 0603M
footprint 0603L
footprint 0603_HV
footprint 0603S
pins: 1, 2

## RG1608P-1472-B-T5
designator R?  ValueDisplayed: 14.7k  (hidden comment: RG1608P-1472-B-T5)
RES, 14.7 k, 0.1%, 0.1 W, 0603; Manufacturer: Susumu Co Ltd; CompType: Resistor; Value: 14.7k; Res_ohm: 14700; Value_Code: 14k7; Tolerance_%: 0.1; Value2: 0.1W; VDC_V: 75; TempCo: 25 ppm/C; SizeArea_mm2: 1.28; SizeX_mm: 1.6; SizeY_mm: 0.8; SizeZ_mm: 1; EIA_Code: E192; U/M: EA; AEC Category: Q200
signal-integrity model Resistor
simulation model Resistor
footprint 0603
footprint 0603M
footprint 0603L
footprint 0603_HV
footprint 0603S
pins: 1, 2

## RG1608P-1541-B-T5
designator R?  ValueDisplayed: 1.54k  (hidden comment: RG1608P-1541-B-T5)
RES, 1.54 k, 0.1%, 0.1 W, 0603; Manufacturer: Susumu Co Ltd; CompType: Resistor; Value: 1.54k; Res_ohm: 1540; Value_Code: 1k54; Tolerance_%: 0.1; Value2: 0.1W; VDC_V: 75; TempCo: 25 ppm/C; SizeArea_mm2: 1.28; SizeX_mm: 1.6; SizeY_mm: 0.8; SizeZ_mm: 1; EIA_Code: E192; U/M: EA; AEC Category: Q200
signal-integrity model Resistor
simulation model Resistor
footprint 0603
footprint 0603M
footprint 0603L
footprint 0603_HV
footprint 0603S
pins: 1, 2

## RG1608P-1542-B-T5
designator R?  ValueDisplayed: 15.4k  (hidden comment: RG1608P-1542-B-T5)
RES, 15.4 k, 0.1%, 0.1 W, 0603; Manufacturer: Susumu Co Ltd; CompType: Resistor; Value: 15.4k; Res_ohm: 15400; Value_Code: 15k4; Tolerance_%: 0.1; Value2: 0.1W; VDC_V: 75; TempCo: 25 ppm/C; SizeArea_mm2: 1.28; SizeX_mm: 1.6; SizeY_mm: 0.8; SizeZ_mm: 1; EIA_Code: E192; U/M: EA; AEC Category: Q200
signal-integrity model Resistor
simulation model Resistor
footprint 0603
footprint 0603M
footprint 0603L
footprint 0603_HV
footprint 0603S
pins: 1, 2

## RG1608P-1581-B-T5
designator R?  ValueDisplayed: 1.58k  (hidden comment: RG1608P-1581-B-T5)
RES, 1.58 k, 0.1%, 0.1 W, 0603; Manufacturer: Susumu Co Ltd; CompType: Resistor; Value: 1.58k; Res_ohm: 1580; Value_Code: 1k58; Tolerance_%: 0.1; Value2: 0.1W; VDC_V: 75; TempCo: 25 ppm/C; SizeArea_mm2: 1.28; SizeX_mm: 1.6; SizeY_mm: 0.8; SizeZ_mm: 1; EIA_Code: E192; U/M: EA; AEC Category: Q200
signal-integrity model Resistor
simulation model Resistor
footprint 0603
footprint 0603M
footprint 0603L
footprint 0603_HV
footprint 0603S
pins: 1, 2

## RG1608P-1620-B-T5
designator R?  ValueDisplayed: 162  (hidden comment: RG1608P-1620-B-T5)
RES, 162, 0.1%, 0.1 W, 0603; Manufacturer: Susumu Co Ltd; CompType: Resistor; Value: 162; Value_Code: 162R; Tolerance_%: 0.1; Value2: 0.1W; VDC_V: 75; TempCo: 25 ppm/C; SizeArea_mm2: 1.28; SizeX_mm: 1.6; SizeY_mm: 0.8; SizeZ_mm: 1; EIA_Code: E192; U/M: EA; AEC Category: Q200
signal-integrity model Resistor
simulation model Resistor
footprint 0603
footprint 0603M
footprint 0603L
footprint 0603_HV
footprint 0603S
pins: 1, 2

## RG1608P-1651-B-T5
designator R?  ValueDisplayed: 1.65k  (hidden comment: RG1608P-1651-B-T5)
RES, 1.65 k, 0.1%, 0.1 W, 0603; Manufacturer: Susumu Co Ltd; CompType: Resistor; Value: 1.65k; Res_ohm: 1650; Value_Code: 1k65; Tolerance_%: 0.1; Value2: 0.1W; VDC_V: 75; TempCo: 25 ppm/C; SizeArea_mm2: 1.28; SizeX_mm: 1.6; SizeY_mm: 0.8; SizeZ_mm: 1; EIA_Code: E192; U/M: EA; AEC Category: Q200
signal-integrity model Resistor
simulation model Resistor
footprint 0603
footprint 0603M
footprint 0603L
footprint 0603_HV
footprint 0603S
pins: 1, 2

## RG1608P-1652-B-T5
designator R?  ValueDisplayed: 16.5k  (hidden comment: RG1608P-1652-B-T5)
RES, 16.5 k, 0.1%, 0.1 W, 0603; Manufacturer: Susumu Co Ltd; CompType: Resistor; Value: 16.5k; Res_ohm: 16500; Value_Code: 16k5; Tolerance_%: 0.1; Value2: 0.1W; VDC_V: 75; TempCo: 25 ppm/C; SizeArea_mm2: 1.28; SizeX_mm: 1.6; SizeY_mm: 0.8; SizeZ_mm: 1; EIA_Code: E192; U/M: EA; AEC Category: Q200; Green_Lifecycle: Active; Green_REACh: Passed
signal-integrity model Resistor
simulation model Resistor
footprint 0603
footprint 0603M
footprint 0603L
footprint 0603_HV
footprint 0603S
pins: 1, 2

## RG1608P-1691-B-T5
designator R?  ValueDisplayed: 1.69k  (hidden comment: RG1608P-1691-B-T5)
RES, 1.69 k, 0.1%, 0.1 W, 0603; Manufacturer: Susumu Co Ltd; CompType: Resistor; Value: 1.69k; Res_ohm: 1690; Value_Code: 1k69; Tolerance_%: 0.1; Value2: 0.1W; VDC_V: 75; TempCo: 25 ppm/C; SizeArea_mm2: 1.28; SizeX_mm: 1.6; SizeY_mm: 0.8; SizeZ_mm: 1; EIA_Code: E192; U/M: EA; AEC Category: Q200
signal-integrity model Resistor
simulation model Resistor
footprint 0603
footprint 0603M
footprint 0603L
footprint 0603_HV
footprint 0603S
pins: 1, 2

## RG1608P-1742-B-T5
designator R?  ValueDisplayed: 17.4k  (hidden comment: RG1608P-1742-B-T5)
RES, 17.4 k, 0.1%, 0.1 W, 0603; Manufacturer: Susumu Co Ltd; CompType: Resistor; Value: 17.4k; Res_ohm: 17400; Value_Code: 17k4; Tolerance_%: 0.1; Value2: 0.1W; VDC_V: 75; TempCo: 25 ppm/C; SizeArea_mm2: 1.28; SizeX_mm: 1.6; SizeY_mm: 0.8; SizeZ_mm: 1; EIA_Code: E192; U/M: EA; AEC Category: Q200
signal-integrity model Resistor
simulation model Resistor
footprint 0603
footprint 0603M
footprint 0603L
footprint 0603_HV
footprint 0603S
pins: 1, 2

## RG1608P-1821-B-T5
designator R?  ValueDisplayed: 1.82k  (hidden comment: RG1608P-1821-B-T5)
RES, 1.82 k, 0.1%, 0.1 W, 0603; Manufacturer: Susumu Co Ltd; CompType: Resistor; Value: 1.82k; Res_ohm: 1820; Value_Code: 1k82; Tolerance_%: 0.1; Value2: 0.1W; VDC_V: 75; TempCo: 25 ppm/C; SizeArea_mm2: 1.28; SizeX_mm: 1.6; SizeY_mm: 0.8; SizeZ_mm: 1; EIA_Code: E192; U/M: EA; AEC Category: Q200
signal-integrity model Resistor
simulation model Resistor
footprint 0603
footprint 0603M
footprint 0603L
footprint 0603_HV
footprint 0603S
pins: 1, 2

## RG1608P-1872-B-T5
designator R?  ValueDisplayed: 18.7k  (hidden comment: RG1608P-1872-B-T5)
RES, 18.7 k, 0.1%, 0.1 W, 0603; Manufacturer: Susumu Co Ltd; CompType: Resistor; Value: 18.7k; Res_ohm: 18700; Value_Code: 18k7; Tolerance_%: 0.1; Value2: 0.1W; VDC_V: 75; TempCo: 25 ppm/C; SizeArea_mm2: 1.28; SizeX_mm: 1.6; SizeY_mm: 0.8; SizeZ_mm: 1; EIA_Code: E192; U/M: EA; AEC Category: Q200
signal-integrity model Resistor
simulation model Resistor
footprint 0603
footprint 0603M
footprint 0603L
footprint 0603_HV
footprint 0603S
pins: 1, 2

## RG1608P-1911-B-T5
designator R?  ValueDisplayed: 1.91k  (hidden comment: RG1608P-1911-B-T5)
RES, 1.91 k, 0.1%, 0.1 W, 0603; Manufacturer: Susumu Co Ltd; CompType: Resistor; Value: 1.91k; Res_ohm: 1910; Value_Code: 1k91; Tolerance_%: 0.1; Value2: 0.1W; VDC_V: 75; TempCo: 25 ppm/C; SizeArea_mm2: 1.28; SizeX_mm: 1.6; SizeY_mm: 0.8; SizeZ_mm: 1; EIA_Code: E192; U/M: EA; AEC Category: Q200
signal-integrity model Resistor
simulation model Resistor
footprint 0603
footprint 0603M
footprint 0603L
footprint 0603_HV
footprint 0603S
pins: 1, 2

## RG1608P-2101-B-T5
designator R?  ValueDisplayed: 2.10k  (hidden comment: RG1608P-2101-B-T5)
RES, 2.10 k, 0.1%, 0.1 W, 0603; Manufacturer: Susumu Co Ltd; CompType: Resistor; Value: 2.10k; Res_ohm: 2100; Value_Code: 2k10; Tolerance_%: 0.1; Value2: 0.1W; VDC_V: 75; TempCo: 25 ppm/C; SizeArea_mm2: 1.28; SizeX_mm: 1.6; SizeY_mm: 0.8; SizeZ_mm: 1; EIA_Code: E192; U/M: EA; AEC Category: Q200
signal-integrity model Resistor
simulation model Resistor
footprint 0603
footprint 0603M
footprint 0603L
footprint 0603_HV
footprint 0603S
pins: 1, 2

## RG1608P-2151-B-T5
designator R?  ValueDisplayed: 2.15k  (hidden comment: RG1608P-2151-B-T5)
RES, 2.15 k, 0.1%, 0.1 W, 0603; Manufacturer: Susumu Co Ltd; CompType: Resistor; Value: 2.15k; Res_ohm: 2150; Value_Code: 2k15; Tolerance_%: 0.1; Value2: 0.1W; VDC_V: 75; TempCo: 25 ppm/C; SizeArea_mm2: 1.28; SizeX_mm: 1.6; SizeY_mm: 0.8; SizeZ_mm: 1; EIA_Code: E192; U/M: EA; AEC Category: Q200
signal-integrity model Resistor
simulation model Resistor
footprint 0603
footprint 0603M
footprint 0603L
footprint 0603_HV
footprint 0603S
pins: 1, 2

## RG1608P-2210-B-T5
designator R?  ValueDisplayed: 221  (hidden comment: RG1608P-2210-B-T5)
RES, 221, 0.1%, 0.1 W, 0603; Manufacturer: Susumu Co Ltd; CompType: Resistor; Value: 221; Value_Code: 221R; Tolerance_%: 0.1; Value2: 0.1W; VDC_V: 75; TempCo: 25 ppm/C; SizeArea_mm2: 1.28; SizeX_mm: 1.6; SizeY_mm: 0.8; SizeZ_mm: 1; EIA_Code: E192; U/M: EA; AEC Category: Q200
signal-integrity model Resistor
simulation model Resistor
footprint 0603
footprint 0603M
footprint 0603L
footprint 0603_HV
footprint 0603S
pins: 1, 2

## RG1608P-2211-B-T5
designator R?  ValueDisplayed: 2.21k  (hidden comment: RG1608P-2211-B-T5)
RES, 2.21 k, 0.1%, 0.1 W, 0603; Manufacturer: Susumu Co Ltd; CompType: Resistor; Value: 2.21k; Res_ohm: 2210; Value_Code: 2k21; Tolerance_%: 0.1; Value2: 0.1W; VDC_V: 75; TempCo: 25 ppm/C; SizeArea_mm2: 1.28; SizeX_mm: 1.6; SizeY_mm: 0.8; SizeZ_mm: 1; EIA_Code: E192; U/M: EA; AEC Category: Q200
signal-integrity model Resistor
simulation model Resistor
footprint 0603
footprint 0603M
footprint 0603L
footprint 0603_HV
footprint 0603S
pins: 1, 2

## RG1608P-2212-B-T5
designator R?  ValueDisplayed: 22.1k  (hidden comment: RG1608P-2212-B-T5)
RES, 22.1 k, 0.1%, 0.1 W, 0603; Manufacturer: Susumu Co Ltd; CompType: Resistor; Value: 22.1k; Res_ohm: 22100; Value_Code: 22k1; Tolerance_%: 0.1; Value2: 0.1W; VDC_V: 75; TempCo: 25 ppm/C; SizeArea_mm2: 1.28; SizeX_mm: 1.6; SizeY_mm: 0.8; SizeZ_mm: 1; EIA_Code: E192; U/M: EA; AEC Category: Q200
signal-integrity model Resistor
simulation model Resistor
footprint 0603
footprint 0603M
footprint 0603L
footprint 0603_HV
footprint 0603S
pins: 1, 2

## RG1608P-2213-B-T5
designator R?  ValueDisplayed: 221k  (hidden comment: RG1608P-2213-B-T5)
RES, 221 k, 0.1%, 0.1 W, 0603; Manufacturer: Susumu Co Ltd; CompType: Resistor; Value: 221k; Res_ohm: 221000; Tolerance_%: 0.1; Value2: 0.1W; VDC_V: 75; TempCo: 25 ppm/C; SizeArea_mm2: 1.28; SizeX_mm: 1.6; SizeY_mm: 0.8; SizeZ_mm: 1; EIA_Code: E192; U/M: EA; AEC Category: Q200
signal-integrity model Resistor
simulation model Resistor
footprint 0603
footprint 0603M
footprint 0603L
footprint 0603_HV
footprint 0603S
pins: 1, 2

## RG1608P-2261-B-T5
designator R?  ValueDisplayed: 2.26k  (hidden comment: RG1608P-2261-B-T5)
RES, 2.26 k, 0.1%, 0.1 W, 0603; Manufacturer: Susumu Co Ltd; CompType: Resistor; Value: 2.26k; Res_ohm: 2260; Value_Code: 2k26; Tolerance_%: 0.1; Value2: 0.1W; VDC_V: 75; TempCo: 25 ppm/C; SizeArea_mm2: 1.28; SizeX_mm: 1.6; SizeY_mm: 0.8; SizeZ_mm: 1; EIA_Code: E192; U/M: EA; AEC Category: Q200
signal-integrity model Resistor
simulation model Resistor
footprint 0603
footprint 0603M
footprint 0603L
footprint 0603_HV
footprint 0603S
pins: 1, 2

## RG1608P-2263-B-T5
designator R?  ValueDisplayed: 226k  (hidden comment: RG1608P-2263-B-T5)
RES, 226 k, 0.1%, 0.1 W, 0603; Manufacturer: Susumu Co Ltd; CompType: Resistor; Value: 226k; Res_ohm: 226000; Tolerance_%: 0.1; Value2: 0.1W; VDC_V: 75; TempCo: 25 ppm/C; SizeArea_mm2: 1.28; SizeX_mm: 1.6; SizeY_mm: 0.8; SizeZ_mm: 1; EIA_Code: E192; U/M: EA; AEC Category: Q200
signal-integrity model Resistor
simulation model Resistor
footprint 0603
footprint 0603M
footprint 0603L
footprint 0603_HV
footprint 0603S
pins: 1, 2

## RG1608P-2321-B-T5
designator R?  ValueDisplayed: 2.32k  (hidden comment: RG1608P-2321-B-T5)
RES, 2.32 k, 0.1%, 0.1 W, 0603; Manufacturer: Susumu Co Ltd; CompType: Resistor; Value: 2.32k; Res_ohm: 2320; Value_Code: 2k32; Tolerance_%: 0.1; Value2: 0.1W; VDC_V: 75; TempCo: 25 ppm/C; SizeArea_mm2: 1.28; SizeX_mm: 1.6; SizeY_mm: 0.8; SizeZ_mm: 1; EIA_Code: E192; U/M: EA; AEC Category: Q200
signal-integrity model Resistor
simulation model Resistor
footprint 0603
footprint 0603M
footprint 0603L
footprint 0603_HV
footprint 0603S
pins: 1, 2

## RG1608P-2322-B-T5
designator R?  ValueDisplayed: 23.2k  (hidden comment: RG1608P-2322-B-T5)
RES, 23.2 k, 0.1%, 0.1 W, 0603; Manufacturer: Susumu Co Ltd; CompType: Resistor; Value: 23.2k; Res_ohm: 23200; Value_Code: 23k2; Tolerance_%: 0.1; Value2: 0.1W; VDC_V: 75; TempCo: 25 ppm/C; SizeArea_mm2: 1.28; SizeX_mm: 1.6; SizeY_mm: 0.8; SizeZ_mm: 1; EIA_Code: E192; U/M: EA; AEC Category: Q200
signal-integrity model Resistor
simulation model Resistor
footprint 0603
footprint 0603M
footprint 0603L
footprint 0603_HV
footprint 0603S
pins: 1, 2

## RG1608P-2323-B-T5
designator R?  ValueDisplayed: 232k  (hidden comment: RG1608P-2323-B-T5)
RES, 232 k, 0.1%, 0.1 W, 0603; Manufacturer: Susumu Co Ltd; CompType: Resistor; Value: 232k; Res_ohm: 232000; Tolerance_%: 0.1; Value2: 0.1W; VDC_V: 75; TempCo: 25 ppm/C; SizeArea_mm2: 1.28; SizeX_mm: 1.6; SizeY_mm: 0.8; SizeZ_mm: 1; EIA_Code: E192; U/M: EA; AEC Category: Q200
signal-integrity model Resistor
simulation model Resistor
footprint 0603
footprint 0603M
footprint 0603L
footprint 0603_HV
footprint 0603S
pins: 1, 2

## RG1608P-2371-B-T5
designator R?  ValueDisplayed: 2.37k  (hidden comment: RG1608P-2371-B-T5)
RES, 2.37 k, 0.1%, 0.1 W, 0603; Manufacturer: Susumu Co Ltd; CompType: Resistor; Value: 2.37k; Res_ohm: 2370; Value_Code: 2k37; Tolerance_%: 0.1; Value2: 0.1W; VDC_V: 75; TempCo: 25 ppm/C; SizeArea_mm2: 1.28; SizeX_mm: 1.6; SizeY_mm: 0.8; SizeZ_mm: 1; EIA_Code: E192; U/M: EA; AEC Category: Q200
signal-integrity model Resistor
simulation model Resistor
footprint 0603
footprint 0603M
footprint 0603L
footprint 0603_HV
footprint 0603S
pins: 1, 2

## RG1608P-2431-B-T5
designator R?  ValueDisplayed: 2.43k  (hidden comment: RG1608P-2431-B-T5)
RES, 2.43 k, 0.1%, 0.1 W, 0603; Manufacturer: Susumu Co Ltd; CompType: Resistor; Value: 2.43k; Res_ohm: 2430; Value_Code: 2k43; Tolerance_%: 0.1; Value2: 0.1W; VDC_V: 75; TempCo: 25 ppm/C; SizeArea_mm2: 1.28; SizeX_mm: 1.6; SizeY_mm: 0.8; SizeZ_mm: 1; EIA_Code: E192; U/M: EA; AEC Category: Q200
signal-integrity model Resistor
simulation model Resistor
footprint 0603
footprint 0603M
footprint 0603L
footprint 0603_HV
footprint 0603S
pins: 1, 2

## RG1608P-2490-B-T5
designator R?  ValueDisplayed: 249  (hidden comment: RG1608P-2490-B-T5)
RES, 249, 0.1%, 0.1 W, 0603; Manufacturer: Susumu Co Ltd; CompType: Resistor; Value: 249; Value_Code: 249R; Tolerance_%: 0.1; Value2: 0.1W; VDC_V: 75; TempCo: 25 ppm/C; SizeArea_mm2: 1.28; SizeX_mm: 1.6; SizeY_mm: 0.8; SizeZ_mm: 1; EIA_Code: E192; U/M: EA; AEC Category: Q200
signal-integrity model Resistor
simulation model Resistor
footprint 0603
footprint 0603M
footprint 0603L
footprint 0603_HV
footprint 0603S
pins: 1, 2

## RG1608P-2491-B-T5
designator R?  ValueDisplayed: 2.49k  (hidden comment: RG1608P-2491-B-T5)
RES, 2.49 k, 0.1%, 0.1 W, 0603; Manufacturer: Susumu Co Ltd; CompType: Resistor; Value: 2.49k; Res_ohm: 2490; Value_Code: 2k49; Tolerance_%: 0.1; Value2: 0.1W; VDC_V: 75; TempCo: 25 ppm/C; SizeArea_mm2: 1.28; SizeX_mm: 1.6; SizeY_mm: 0.8; SizeZ_mm: 1; EIA_Code: E192; U/M: EA; AEC Category: Q200; Green_Lifecycle: Active; Green_REACh: Passed
signal-integrity model Resistor
simulation model Resistor
footprint 0603
footprint 0603M
footprint 0603L
footprint 0603_HV
footprint 0603S
pins: 1, 2

## RG1608P-2492-B-T5
designator R?  ValueDisplayed: 24.9k  (hidden comment: RG1608P-2492-B-T5)
RES, 24.9 k, 0.1%, 0.1 W, 0603; Manufacturer: Susumu Co Ltd; CompType: Resistor; Value: 24.9k; Res_ohm: 24900; Value_Code: 24k9; Tolerance_%: 0.1; Value2: 0.1W; VDC_V: 75; TempCo: 25 ppm/C; SizeArea_mm2: 1.28; SizeX_mm: 1.6; SizeY_mm: 0.8; SizeZ_mm: 1; EIA_Code: E192; U/M: EA; AEC Category: Q200
signal-integrity model Resistor
simulation model Resistor
footprint 0603
footprint 0603M
footprint 0603L
footprint 0603_HV
footprint 0603S
pins: 1, 2

## RG1608P-2493-B-T5
designator R?  ValueDisplayed: 249k  (hidden comment: RG1608P-2493-B-T5)
RES, 249 k, 0.1%, 0.1 W, 0603; Manufacturer: Susumu Co Ltd; CompType: Resistor; Value: 249k; Res_ohm: 249000; Tolerance_%: 0.1; Value2: 0.1W; VDC_V: 75; TempCo: 25 ppm/C; SizeArea_mm2: 1.28; SizeX_mm: 1.6; SizeY_mm: 0.8; SizeZ_mm: 1; EIA_Code: E192; U/M: EA; AEC Category: Q200
signal-integrity model Resistor
simulation model Resistor
footprint 0603
footprint 0603M
footprint 0603L
footprint 0603_HV
footprint 0603S
pins: 1, 2

## RG1608P-2551-B-T5
designator R?  ValueDisplayed: 2.55k  (hidden comment: RG1608P-2551-B-T5)
RES, 2.55 k, 0.1%, 0.1 W, 0603; Manufacturer: Susumu Co Ltd; CompType: Resistor; Value: 2.55k; Res_ohm: 2550; Value_Code: 2k55; Tolerance_%: 0.1; Value2: 0.1W; VDC_V: 75; TempCo: 25 ppm/C; SizeArea_mm2: 1.28; SizeX_mm: 1.6; SizeY_mm: 0.8; SizeZ_mm: 1; EIA_Code: E192; U/M: EA; AEC Category: Q200
signal-integrity model Resistor
simulation model Resistor
footprint 0603
footprint 0603M
footprint 0603L
footprint 0603_HV
footprint 0603S
pins: 1, 2

## RG1608P-2552-B-T5
designator R?  ValueDisplayed: 25.5k  (hidden comment: RG1608P-2552-B-T5)
RES, 25.5 k, 0.1%, 0.1 W, 0603; Manufacturer: Susumu Co Ltd; CompType: Resistor; Value: 25.5k; Res_ohm: 25500; Value_Code: 25k5; Tolerance_%: 0.1; Value2: 0.1W; VDC_V: 75; TempCo: 25 ppm/C; SizeArea_mm2: 1.28; SizeX_mm: 1.6; SizeY_mm: 0.8; SizeZ_mm: 1; EIA_Code: E192; U/M: EA; AEC Category: Q200; Green_Lifecycle: Active; Green_REACh: Passed
signal-integrity model Resistor
simulation model Resistor
footprint 0603
footprint 0603M
footprint 0603L
footprint 0603_HV
footprint 0603S
pins: 1, 2

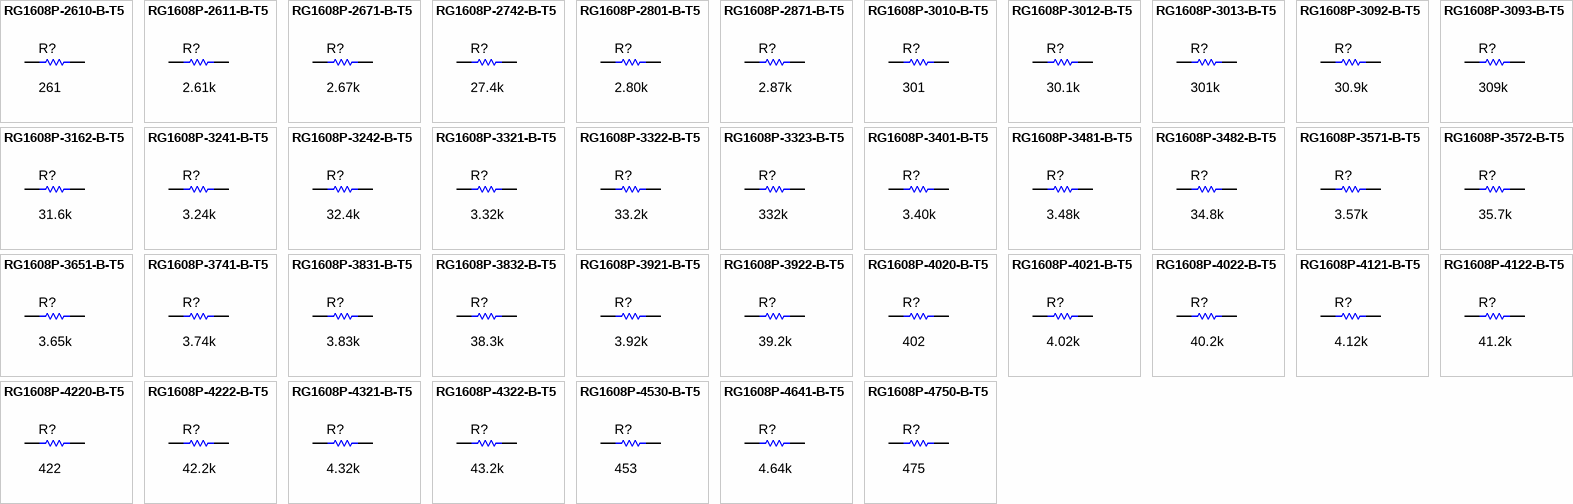
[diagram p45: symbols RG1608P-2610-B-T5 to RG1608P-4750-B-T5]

## RG1608P-2610-B-T5
designator R?  ValueDisplayed: 261  (hidden comment: RG1608P-2610-B-T5)
RES, 261, 0.1%, 0.1 W, 0603; Manufacturer: Susumu Co Ltd; CompType: Resistor; Value: 261; Value_Code: 261R; Tolerance_%: 0.1; Value2: 0.1W; VDC_V: 75; TempCo: 25 ppm/C; SizeArea_mm2: 1.28; SizeX_mm: 1.6; SizeY_mm: 0.8; SizeZ_mm: 1; EIA_Code: E192; U/M: EA; AEC Category: Q200
signal-integrity model Resistor
simulation model Resistor
footprint 0603
footprint 0603M
footprint 0603L
footprint 0603_HV
footprint 0603S
pins: 1, 2

## RG1608P-2611-B-T5
designator R?  ValueDisplayed: 2.61k  (hidden comment: RG1608P-2611-B-T5)
RES, 2.61 k, 0.1%, 0.1 W, 0603; Manufacturer: Susumu Co Ltd; CompType: Resistor; Value: 2.61k; Res_ohm: 2610; Value_Code: 2k61; Tolerance_%: 0.1; Value2: 0.1W; VDC_V: 75; TempCo: 25 ppm/C; SizeArea_mm2: 1.28; SizeX_mm: 1.6; SizeY_mm: 0.8; SizeZ_mm: 1; EIA_Code: E192; U/M: EA; AEC Category: Q200
signal-integrity model Resistor
simulation model Resistor
footprint 0603
footprint 0603M
footprint 0603L
footprint 0603_HV
footprint 0603S
pins: 1, 2

## RG1608P-2671-B-T5
designator R?  ValueDisplayed: 2.67k  (hidden comment: RG1608P-2671-B-T5)
RES, 2.67 k, 0.1%, 0.1 W, 0603; Manufacturer: Susumu Co Ltd; CompType: Resistor; Value: 2.67k; Res_ohm: 2670; Value_Code: 2k67; Tolerance_%: 0.1; Value2: 0.1W; VDC_V: 75; TempCo: 25 ppm/C; SizeArea_mm2: 1.28; SizeX_mm: 1.6; SizeY_mm: 0.8; SizeZ_mm: 1; EIA_Code: E192; U/M: EA; AEC Category: Q200
signal-integrity model Resistor
simulation model Resistor
footprint 0603
footprint 0603M
footprint 0603L
footprint 0603_HV
footprint 0603S
pins: 1, 2

## RG1608P-2742-B-T5
designator R?  ValueDisplayed: 27.4k  (hidden comment: RG1608P-2742-B-T5)
RES, 27.4 k, 0.1%, 0.1 W, 0603; Manufacturer: Susumu Co Ltd; CompType: Resistor; Value: 27.4k; Res_ohm: 27400; Value_Code: 27k4; Tolerance_%: 0.1; Value2: 0.1W; VDC_V: 75; TempCo: 25 ppm/C; SizeArea_mm2: 1.28; SizeX_mm: 1.6; SizeY_mm: 0.8; SizeZ_mm: 1; EIA_Code: E192; U/M: EA; AEC Category: Q200
signal-integrity model Resistor
simulation model Resistor
footprint 0603
footprint 0603M
footprint 0603L
footprint 0603_HV
footprint 0603S
pins: 1, 2

## RG1608P-2801-B-T5
designator R?  ValueDisplayed: 2.80k  (hidden comment: RG1608P-2801-B-T5)
RES, 2.80 k, 0.1%, 0.1 W, 0603; Manufacturer: Susumu Co Ltd; CompType: Resistor; Value: 2.80k; Res_ohm: 2800; Value_Code: 2k80; Tolerance_%: 0.1; Value2: 0.1W; VDC_V: 75; TempCo: 25 ppm/C; SizeArea_mm2: 1.28; SizeX_mm: 1.6; SizeY_mm: 0.8; SizeZ_mm: 1; EIA_Code: E192; U/M: EA; AEC Category: Q200
signal-integrity model Resistor
simulation model Resistor
footprint 0603
footprint 0603M
footprint 0603L
footprint 0603_HV
footprint 0603S
pins: 1, 2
